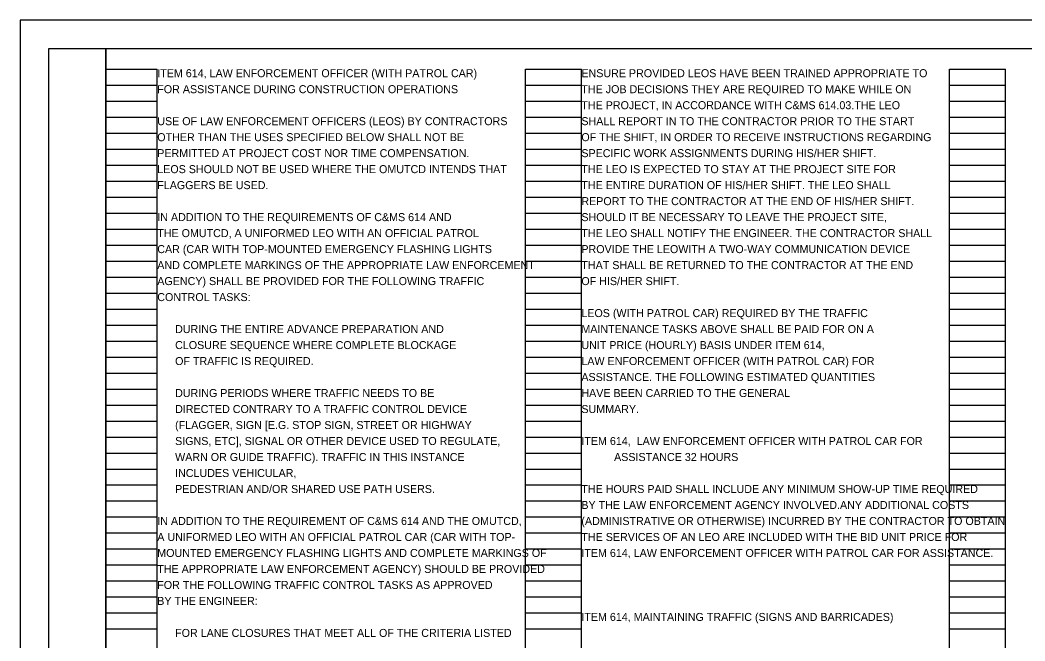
# Model space of a CAD drawing. Extents: x 0 to 34, y 0 to 22.
# Drawn here: x 0 to 17.58, y 11.13 to 22 of the extents above; entities that cross this region are included whole.
import ezdxf

# ---------------------------------------------------------------- set-up
doc = ezdxf.new("R2010")
doc.units = 0
for name, color, linetype in [('SH_Border', 7, 'Continuous'), ('SH_Cut_Line', 7, 'Continuous'), ('SH_Data', 7, 'Continuous'), ('SH_Text', 7, 'Continuous')]:
    doc.layers.add(name, color=color, linetype=linetype)

msp = doc.modelspace()

# ---------------------------------------------------------------- linework, layer by layer
at = {"layer": 'SH_Border'}
for points in [[(0.5, 21.5), (1.5, 21.5), (1.5, 0.5), (0.5, 0.5)], [(1.5, 21.5), (33.5, 21.5), (33.5, 0.5), (1.5, 0.5)]]:
    msp.add_lwpolyline(points, close=True, dxfattribs=at)
at = {"layer": 'SH_Cut_Line'}
msp.add_lwpolyline([(0, 0), (34, 0), (34, 22), (0, 22)], close=True, dxfattribs=at)
at = {"layer": 'SH_Data'}
for p, q in [((1.5, 0.98), (1.5, 21.14)), ((1.5, 21.14), (2.4, 21.14)), ((2.4, 0.98), (2.4, 21.14)), ((8.84, 0.98), (8.84, 21.14)), ((8.84, 21.14), (9.82, 21.14)), ((9.82, 0.98), (9.82, 21.14)), ((16.26, 0.98), (16.26, 21.14)), ((16.26, 21.14), (17.24, 21.14)), ((17.24, 0.98), (17.24, 21.14)), ((1.5, 20.86), (2.4, 20.86)), ((8.84, 20.86), (9.82, 20.86)), ((16.26, 20.86), (17.24, 20.86)), ((1.5, 20.58), (2.4, 20.58)), ((8.84, 20.58), (9.82, 20.58)), ((16.26, 20.58), (17.24, 20.58)), ((1.5, 20.3), (2.4, 20.3)), ((8.84, 20.3), (9.82, 20.3)), ((16.26, 20.3), (17.24, 20.3)), ((1.5, 20.02), (2.4, 20.02)), ((8.84, 20.02), (9.82, 20.02)), ((16.26, 20.02), (17.24, 20.02)), ((1.5, 19.74), (2.4, 19.74)), ((8.84, 19.74), (9.82, 19.74)), ((16.26, 19.74), (17.24, 19.74)), ((1.5, 19.46), (2.4, 19.46)), ((8.84, 19.46), (9.82, 19.46)), ((16.26, 19.46), (17.24, 19.46)), ((1.5, 19.18), (2.4, 19.18)), ((8.84, 19.18), (9.82, 19.18)), ((16.26, 19.18), (17.24, 19.18)), ((1.5, 18.9), (2.4, 18.9)), ((8.84, 18.9), (9.82, 18.9)), ((16.26, 18.9), (17.24, 18.9)), ((1.5, 18.62), (2.4, 18.62)), ((8.84, 18.62), (9.82, 18.62)), ((16.26, 18.62), (17.24, 18.62)), ((1.5, 18.34), (2.4, 18.34)), ((8.84, 18.34), (9.82, 18.34)), ((16.26, 18.34), (17.24, 18.34)), ((1.5, 18.06), (2.4, 18.06)), ((8.84, 18.06), (9.82, 18.06)), ((16.26, 18.06), (17.24, 18.06)), ((1.5, 17.78), (2.4, 17.78)), ((8.84, 17.78), (9.82, 17.78)), ((16.26, 17.78), (17.24, 17.78)), ((1.5, 17.5), (2.4, 17.5)), ((8.84, 17.5), (9.82, 17.5)), ((16.26, 17.5), (17.24, 17.5)), ((1.5, 17.22), (2.4, 17.22)), ((8.84, 17.22), (9.82, 17.22)), ((16.26, 17.22), (17.24, 17.22)), ((1.5, 16.94), (2.4, 16.94)), ((8.84, 16.94), (9.82, 16.94)), ((16.26, 16.94), (17.24, 16.94)), ((1.5, 16.66), (2.4, 16.66)), ((8.84, 16.66), (9.82, 16.66)), ((16.26, 16.66), (17.24, 16.66)), ((1.5, 16.38), (2.4, 16.38)), ((8.84, 16.38), (9.82, 16.38)), ((16.26, 16.38), (17.24, 16.38)), ((1.5, 16.1), (2.4, 16.1)), ((8.84, 16.1), (9.82, 16.1)), ((16.26, 16.1), (17.24, 16.1)), ((1.5, 15.82), (2.4, 15.82)), ((8.84, 15.82), (9.82, 15.82)), ((16.26, 15.82), (17.24, 15.82)), ((1.5, 15.54), (2.4, 15.54)), ((8.84, 15.54), (9.82, 15.54)), ((16.26, 15.54), (17.24, 15.54)), ((1.5, 15.26), (2.4, 15.26)), ((8.84, 15.26), (9.82, 15.26)), ((16.26, 15.26), (17.24, 15.26)), ((1.5, 14.98), (2.4, 14.98)), ((8.84, 14.98), (9.82, 14.98)), ((16.26, 14.98), (17.24, 14.98)), ((1.5, 14.7), (2.4, 14.7)), ((8.84, 14.7), (9.82, 14.7)), ((16.26, 14.7), (17.24, 14.7)), ((1.5, 14.42), (2.4, 14.42)), ((8.84, 14.42), (9.82, 14.42)), ((16.26, 14.42), (17.24, 14.42)), ((1.5, 14.14), (2.4, 14.14)), ((8.84, 14.14), (9.82, 14.14)), ((16.26, 14.14), (17.24, 14.14)), ((1.5, 13.86), (2.4, 13.86)), ((8.84, 13.86), (9.82, 13.86)), ((16.26, 13.86), (17.24, 13.86)), ((1.5, 13.58), (2.4, 13.58)), ((8.84, 13.58), (9.82, 13.58)), ((16.26, 13.58), (17.24, 13.58)), ((1.5, 13.3), (2.4, 13.3)), ((8.84, 13.3), (9.82, 13.3)), ((16.26, 13.3), (17.24, 13.3)), ((1.5, 13.02), (2.4, 13.02)), ((8.84, 13.02), (9.82, 13.02)), ((16.26, 13.02), (17.24, 13.02)), ((1.5, 12.74), (2.4, 12.74)), ((8.84, 12.74), (9.82, 12.74)), ((16.26, 12.74), (17.24, 12.74)), ((1.5, 12.46), (2.4, 12.46)), ((8.84, 12.46), (9.82, 12.46)), ((16.26, 12.46), (17.24, 12.46)), ((1.5, 12.18), (2.4, 12.18)), ((8.84, 12.18), (9.82, 12.18)), ((16.26, 12.18), (17.24, 12.18)), ((1.5, 11.9), (2.4, 11.9)), ((8.84, 11.9), (9.82, 11.9)), ((16.26, 11.9), (17.24, 11.9)), ((1.5, 11.62), (2.4, 11.62)), ((8.84, 11.62), (9.82, 11.62)), ((16.26, 11.62), (17.24, 11.62)), ((1.5, 11.34), (2.4, 11.34)), ((8.84, 11.34), (9.82, 11.34)), ((16.26, 11.34), (17.24, 11.34))]:
    msp.add_line(p, q, dxfattribs=at)

# ---------------------------------------------------------------- texts
at = {"layer": 'SH_Text'}
for s, p in [('ITEM 614, LAW ENFORCEMENT OFFICER (WITH PATROL CAR)', (2.4, 21)), ('ENSURE PROVIDED LEOS HAVE BEEN TRAINED APPROPRIATE TO', (9.82, 21)), ('FOR ASSISTANCE DURING CONSTRUCTION OPERATIONS', (2.4, 20.72)), ('THE JOB DECISIONS THEY ARE REQUIRED TO MAKE WHILE ON', (9.82, 20.72)), ('THE PROJECT, IN ACCORDANCE WITH C&MS 614.03.THE LEO', (9.82, 20.44)), ('USE OF LAW ENFORCEMENT OFFICERS (LEOS) BY CONTRACTORS', (2.4, 20.16)), ('SHALL REPORT IN TO THE CONTRACTOR PRIOR TO THE START', (9.82, 20.16)), ('OTHER THAN THE USES SPECIFIED BELOW SHALL NOT BE', (2.4, 19.88)), ('OF THE SHIFT, IN ORDER TO RECEIVE INSTRUCTIONS REGARDING', (9.82, 19.88)), ('PERMITTED AT PROJECT COST NOR TIME COMPENSATION.', (2.4, 19.6)), ('SPECIFIC WORK ASSIGNMENTS DURING HIS/HER SHIFT.', (9.82, 19.6)), ('LEOS SHOULD NOT BE USED WHERE THE OMUTCD INTENDS THAT', (2.4, 19.32)), ('THE LEO IS EXPECTED TO STAY AT THE PROJECT SITE FOR', (9.82, 19.32)), ('FLAGGERS BE USED.', (2.4, 19.04)), ('THE ENTIRE DURATION OF HIS/HER SHIFT. THE LEO SHALL', (9.82, 19.04)), ('REPORT TO THE CONTRACTOR AT THE END OF HIS/HER SHIFT.', (9.82, 18.76)), ('IN ADDITION TO THE REQUIREMENTS OF C&MS 614 AND', (2.4, 18.48)), ('SHOULD IT BE NECESSARY TO LEAVE THE PROJECT SITE,', (9.82, 18.48)), ('THE OMUTCD, A UNIFORMED LEO WITH AN OFFICIAL PATROL', (2.4, 18.2)), ('THE LEO SHALL NOTIFY THE ENGINEER. THE CONTRACTOR SHALL', (9.82, 18.2)), ('CAR (CAR WITH TOP-MOUNTED EMERGENCY FLASHING LIGHTS', (2.4, 17.92)), ('PROVIDE THE LEOWITH A TWO-WAY COMMUNICATION DEVICE', (9.82, 17.92)), ('AND COMPLETE MARKINGS OF THE APPROPRIATE LAW ENFORCEMENT', (2.4, 17.64)), ('THAT SHALL BE RETURNED TO THE CONTRACTOR AT THE END', (9.82, 17.64)), ('AGENCY) SHALL BE PROVIDED FOR THE FOLLOWING TRAFFIC', (2.4, 17.36)), ('OF HIS/HER SHIFT.', (9.82, 17.36)), ('CONTROL TASKS:', (2.4, 17.08)), ('LEOS (WITH PATROL CAR) REQUIRED BY THE TRAFFIC', (9.82, 16.8)), ('      DURING THE ENTIRE ADVANCE PREPARATION AND', (2.4, 16.52)), ('MAINTENANCE TASKS ABOVE SHALL BE PAID FOR ON A', (9.82, 16.52)), ('      CLOSURE SEQUENCE WHERE COMPLETE BLOCKAGE', (2.4, 16.24)), ('UNIT PRICE (HOURLY) BASIS UNDER ITEM 614,', (9.82, 16.24)), ('      OF TRAFFIC IS REQUIRED.', (2.4, 15.96)), ('LAW ENFORCEMENT OFFICER (WITH PATROL CAR) FOR', (9.82, 15.96)), ('ASSISTANCE. THE FOLLOWING ESTIMATED QUANTITIES', (9.82, 15.68)), ('      DURING PERIODS WHERE TRAFFIC NEEDS TO BE', (2.4, 15.4)), ('HAVE BEEN CARRIED TO THE GENERAL', (9.82, 15.4)), ('      DIRECTED CONTRARY TO A TRAFFIC CONTROL DEVICE', (2.4, 15.12)), ('SUMMARY.', (9.82, 15.12)), ('      (FLAGGER, SIGN [E.G. STOP SIGN, STREET OR HIGHWAY', (2.4, 14.84)), ('      SIGNS, ETC], SIGNAL OR OTHER DEVICE USED TO REGULATE,', (2.4, 14.56)), ('ITEM 614,  LAW ENFORCEMENT OFFICER WITH PATROL CAR FOR', (9.82, 14.56)), ('      WARN OR GUIDE TRAFFIC). TRAFFIC IN THIS INSTANCE', (2.4, 14.28)), ('           ASSISTANCE 32 HOURS', (9.82, 14.28)), ('      INCLUDES VEHICULAR,', (2.4, 14)), ('      PEDESTRIAN AND/OR SHARED USE PATH USERS.', (2.4, 13.72)), ('THE HOURS PAID SHALL INCLUDE ANY MINIMUM SHOW-UP TIME REQUIRED', (9.82, 13.72)), ('BY THE LAW ENFORCEMENT AGENCY INVOLVED.ANY ADDITIONAL COSTS', (9.82, 13.44)), ('IN ADDITION TO THE REQUIREMENT OF C&MS 614 AND THE OMUTCD,', (2.4, 13.16)), ('(ADMINISTRATIVE OR OTHERWISE) INCURRED BY THE CONTRACTOR TO OBTAIN', (9.82, 13.16)), ('A UNIFORMED LEO WITH AN OFFICIAL PATROL CAR (CAR WITH TOP-', (2.4, 12.88)), ('THE SERVICES OF AN LEO ARE INCLUDED WITH THE BID UNIT PRICE FOR', (9.82, 12.88)), ('MOUNTED EMERGENCY FLASHING LIGHTS AND COMPLETE MARKINGS OF', (2.4, 12.6)), ('ITEM 614, LAW ENFORCEMENT OFFICER WITH PATROL CAR FOR ASSISTANCE.', (9.82, 12.6)), ('THE APPROPRIATE LAW ENFORCEMENT AGENCY) SHOULD BE PROVIDED', (2.4, 12.32)), ('FOR THE FOLLOWING TRAFFIC CONTROL TASKS AS APPROVED', (2.4, 12.04)), ('BY THE ENGINEER:', (2.4, 11.76)), ('ITEM 614, MAINTAINING TRAFFIC (SIGNS AND BARRICADES)', (9.82, 11.48)), ('      FOR LANE CLOSURES THAT MEET ALL OF THE CRITERIA LISTED', (2.4, 11.2))]:
    msp.add_text(s, height=0.14, dxfattribs=at).set_placement(p)

doc.saveas('drawing.dxf')
